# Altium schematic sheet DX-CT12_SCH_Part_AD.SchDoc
size A4
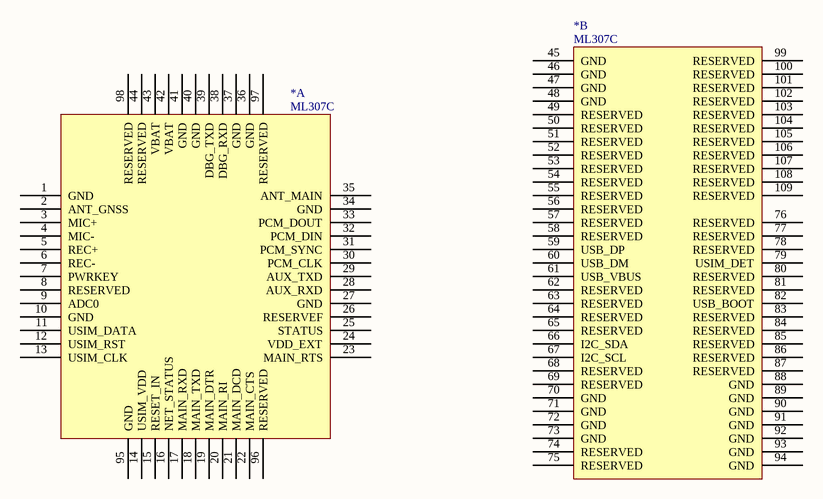
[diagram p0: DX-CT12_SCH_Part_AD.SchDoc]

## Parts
(Parts that share a designator on the sheet are numbered #1, #2 ... from top to bottom, then left to right.)
*#1  ML307C  [ML307C]  (part B of 2)
*#2  ML307C  [ML307C]  (part A of 2)

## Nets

Not connected (* = marked no-connect by the designer): *#1 45(GND) 46(GND) 47(GND) 48(GND) 49(RESERVED) 50(RESERVED) 51(RESERVED) 52(RESERVED) 53(RESERVED) 54(RESERVED) 55(RESERVED) 56(RESERVED) 57(RESERVED) 58(RESERVED) 59(USB_DP) 60(USB_DM) 61(USB_VBUS) 62(RESERVED) 63(RESERVED) 64(RESERVED) 65(RESERVED) 66(I2C_SDA) 67(I2C_SCL) 68(RESERVED) 69(RESERVED) 70(GND) 71(GND) 72(GND) 73(GND) 74(RESERVED) 75(RESERVED) 76(RESERVED) 77(RESERVED) 78(RESERVED) 79(USIM_DET) 80(RESERVED) 81(RESERVED) 82(USB_BOOT) 83(RESERVED) 84(RESERVED) 85(RESERVED) 86(RESERVED) 87(RESERVED) 88(GND) 89(GND) 90(GND) 91(GND) 92(GND) 93(GND) 94(GND) 99(RESERVED) 100(RESERVED) 101(RESERVED) 102(RESERVED) 103(RESERVED) 104(RESERVED) 105(RESERVED) 106(RESERVED) 107(RESERVED) 108(RESERVED) 109(RESERVED); *#2 1(GND) 2(ANT_GNSS) 3(MIC+) 4(MIC-) 5(REC+) 6(REC-) 7(PWRKEY) 8(RESERVED) 9(ADC0) 10(GND) 11(USIM_DATA) 12(USIM_RST) 13(USIM_CLK) 14(USIM_VDD) 15(RESET_IN) 16(NET_STATUS) 17(MAIN_RXD) 18(MAIN_TXD) 19(MAIN_DTR) 20(MAIN_RI) 21(MAIN_DCD) 22(MAIN_CTS) 23(MAIN_RTS) 24(VDD_EXT) 25(STATUS) 26(RESERVEF) 27(GND) 28(AUX_RXD) 29(AUX_TXD) 30(PCM_CLK) 31(PCM_SYNC) 32(PCM_DIN) 33(PCM_DOUT) 34(GND) 35(ANT_MAIN) 36(GND) 37(GND) 38(DBG_RXD) 39(DBG_TXD) 40(GND) 41(GND) 42(VBAT) 43(VBAT) 44(RESERVED) 95(GND) 96(RESERVED) 97(RESERVED) 98(RESERVED)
